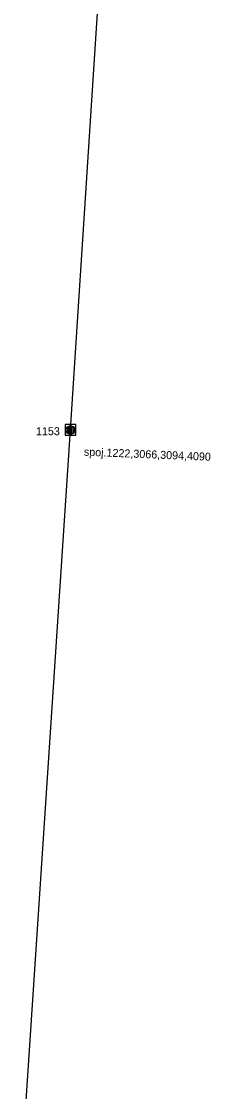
# Model space of a CAD drawing. Extents: x -535557 to -534097, y -1142175 to -1136716.
# Drawn here: x -534420.9 to -534403.3, y -1140603.8 to -1140503.5 of the extents above; entities that cross this region are included whole.
import ezdxf

# ---------------------------------------------------------------- set-up
doc = ezdxf.new("R2010")
doc.units = 0
doc.layers.add('Default', color=7, linetype='Continuous')
doc.layers.add('SS_SZDC', color=7, linetype='Continuous')

# ---------------------------------------------------------------- blocks, each defined once
blk = doc.blocks.new('POINT_DISPLAY')
at = {"layer": 'Default'}
blk.add_line((0, 0), (0, 0), dxfattribs=at)

msp = doc.modelspace()

# ---------------------------------------------------------------- linework, layer by layer
at = {"layer": 'SS_SZDC'}
for p, q in [((-534416.34, -1140541.79), (-534412.869, -1140488.229)), ((-534420.93, -1140611.2), (-534416.34, -1140541.79)), ((-534415.84, -1140541.29), (-534416.84, -1140541.29)), ((-534416.84, -1140541.29), (-534416.84, -1140542.29)), ((-534416.74, -1140541.692), (-534416.641, -1140541.491)), ((-534416.739, -1140541.892), (-534416.74, -1140541.692)), ((-534416.638, -1140542.091), (-534416.739, -1140541.892)), ((-534416.641, -1140541.491), (-534416.442, -1140541.39)), ((-534416.64, -1140541.641), (-534416.639, -1140541.941)), ((-534416.541, -1140541.541), (-534416.442, -1140541.44)), ((-534416.538, -1140542.091), (-534416.541, -1140541.541)), ((-534416.442, -1140541.39), (-534416.242, -1140541.389)), ((-534416.442, -1140541.44), (-534416.437, -1140542.14)), ((-534416.337, -1140542.139), (-534416.342, -1140541.44)), ((-534416.242, -1140541.389), (-534416.041, -1140541.488)), ((-534416.237, -1140542.139), (-534416.242, -1140541.439)), ((-534416.242, -1140541.439), (-534416.141, -1140541.538)), ((-534416.141, -1140541.538), (-534416.138, -1140542.088)), ((-534416.041, -1140541.488), (-534415.94, -1140541.687)), ((-534416.039, -1140541.938), (-534416.04, -1140541.638)), ((-534415.939, -1140541.887), (-534416.038, -1140542.088)), ((-534415.94, -1140541.687), (-534415.939, -1140541.887)), ((-534415.84, -1140542.29), (-534415.84, -1140541.29)), ((-534416.84, -1140542.29), (-534415.84, -1140542.29)), ((-534416.639, -1140541.941), (-534416.538, -1140542.091)), ((-534416.437, -1140542.19), (-534416.638, -1140542.091)), ((-534416.437, -1140542.14), (-534416.237, -1140542.139)), ((-534416.237, -1140542.189), (-534416.437, -1140542.19)), ((-534416.038, -1140542.088), (-534416.237, -1140542.189)), ((-534416.138, -1140542.088), (-534416.039, -1140541.938))]:
    msp.add_line(p, q, dxfattribs=at)

# ---------------------------------------------------------------- block references
msp.add_blockref('POINT_DISPLAY', (-534416.34, -1140541.79), dxfattribs=at)

# ---------------------------------------------------------------- texts
msp.add_text('1153', height=0.75, dxfattribs=at).set_placement((-534419.573, -1140542.279))
msp.add_text('spoj.1222,3066,3094,4090', height=0.74999, rotation=357.67566, dxfattribs=at).set_placement((-534415.105, -1140544.197))

doc.saveas('drawing.dxf')
